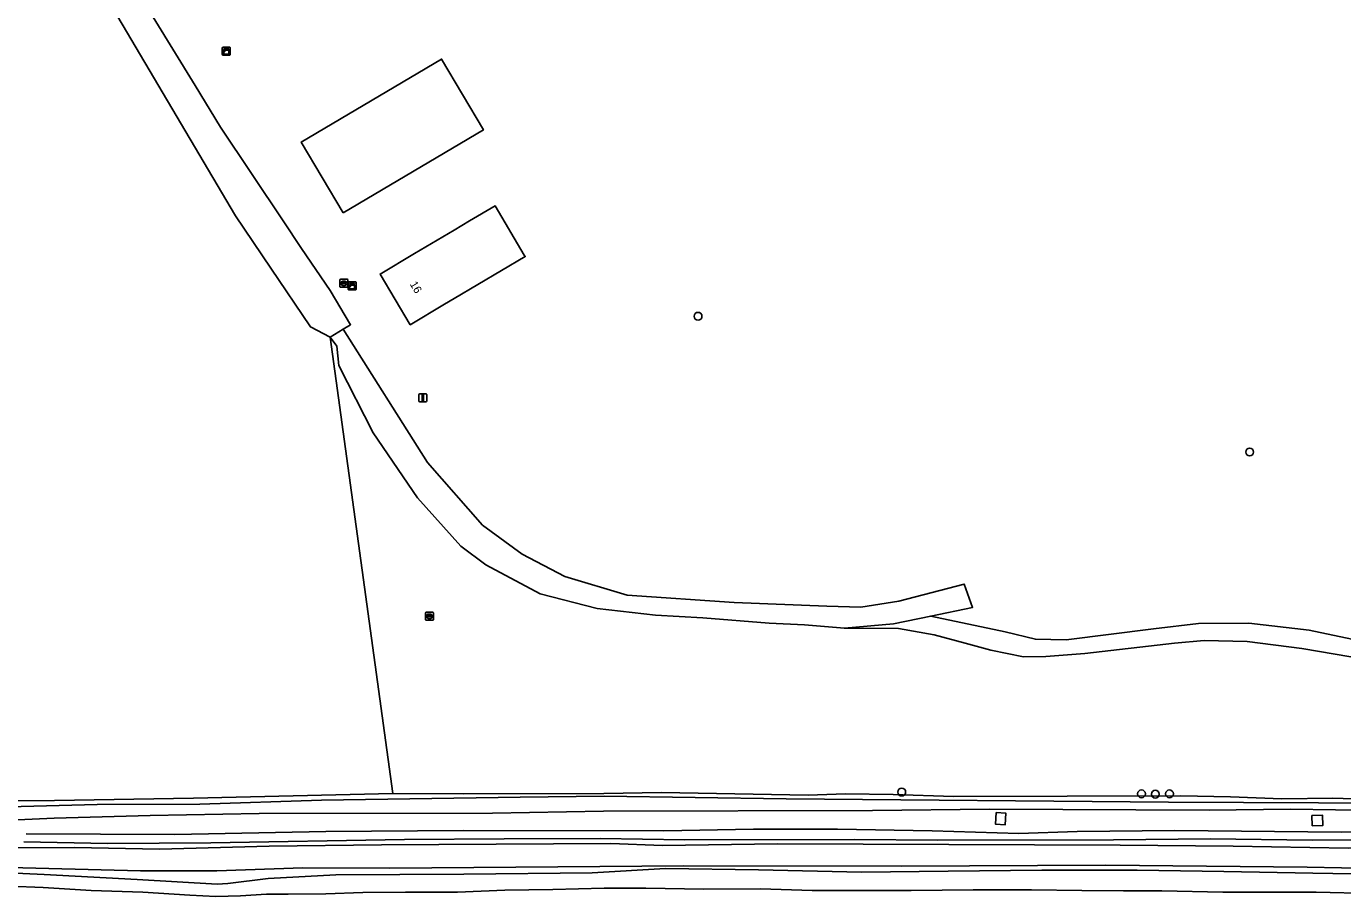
# Model space of a CAD drawing. Extents: x 160203 to 161530, y 379528 to 381797.
# Drawn here: x 160446.6 to 160611, y 379665.5 to 379774.3 of the extents above; entities that cross this region are included whole.
import ezdxf

# ---------------------------------------------------------------- set-up
doc = ezdxf.new("R2010")
doc.units = 0
for name, color, linetype in [('IMGEO_Boom', 7, 'Continuous'), ('IMGEO_Grasland_overig', 7, 'Continuous'), ('IMGEO_Groenvoorziening', 7, 'Continuous'), ('IMGEO_Hek', 7, 'Continuous'), ('IMGEO_Kast', 7, 'Continuous'), ('IMGEO_Lichtmast', 7, 'Continuous'), ('IMGEO_Pand', 7, 'Continuous'), ('IMGEO_Pand_nummerreeks', 7, 'Continuous'), ('IMGEO_Rijbaan_lokaal_gesloten', 7, 'Continuous'), ('IMGEO_Rijbaan_lokaal_halfverhard', 7, 'Continuous'), ('IMGEO_Rijbaan_lokaal_onverhard', 7, 'Continuous'), ('IMGEO_Rioolput', 7, 'Continuous'), ('IMGEO_Voetpad_open', 7, 'Continuous')]:
    doc.layers.add(name, color=color, linetype=linetype)

msp = doc.modelspace()

# ---------------------------------------------------------------- linework, layer by layer
at = {"layer": 'IMGEO_Boom'}
for centre in [(160530.49, 379738.08), (160599.41, 379721.11), (160555.94, 379678.6), (160585.9, 379678.38), (160587.63, 379678.34), (160589.39, 379678.38)]:
    msp.add_circle(centre, 0.489, dxfattribs=at)
at = {"layer": 'IMGEO_Grasland_overig'}
for points in [[(160450.12, 379795.52), (160467.63, 379766.93), (160470.83, 379761.7), (160478.64, 379750), (160480.94, 379746.53), (160484.53, 379741.3), (160487.06, 379737.02), (160486.15, 379736.46), (160496.7, 379719.81), (160503.56, 379711.98), (160508.49, 379708.33), (160513.83, 379705.53), (160521.61, 379703.21), (160534.99, 379702.31), (160546.6, 379701.83), (160550.81, 379701.71), (160555.59, 379702.48), (160563.74, 379704.6), (160564.79, 379701.69), (160559.56, 379700.59), (160568.86, 379698.64), (160572.64, 379697.7), (160576.48, 379697.62), (160587.41, 379699.01), (160593.03, 379699.68), (160599.33, 379699.71), (160606.84, 379698.83), (160615.35, 379697.05)], [(160472.68, 379750.63), (160447.21, 379793.79)], [(160424.45, 379677.34), (160450.09, 379677.56), (160467.43, 379677.83), (160492.33, 379678.43), (160484.53, 379735.46), (160482.04, 379736.75), (160477.11, 379744.07), (160472.68, 379750.63)], [(160617.93, 379694.49), (160605.92, 379696.56), (160599.09, 379697.42), (160593.73, 379697.54), (160590.01, 379697.2), (160578.8, 379695.94), (160573.94, 379695.55), (160571.17, 379695.52), (160567.06, 379696.36), (160563.85, 379697.23), (160560, 379698.24), (160555.54, 379699.04), (160548.78, 379699.07), (160543.77, 379699.51), (160539.38, 379699.73), (160531.09, 379700.4), (160525.19, 379700.71), (160517.9, 379701.55), (160510.76, 379703.37), (160503.96, 379707), (160500.86, 379709.33), (160495.45, 379715.4), (160489.91, 379723.51), (160485.58, 379731.93), (160485.34, 379734.34), (160484.53, 379735.46), (160492.33, 379678.43), (160501.15, 379678.37), (160518.7, 379678.42), (160525.94, 379678.55), (160544.26, 379678.22), (160548.9, 379678.37), (160554.86, 379678.29), (160562.39, 379678.04), (160590.8, 379678.12), (160597.04, 379678), (160603.45, 379677.76), (160609.81, 379677.82), (160617.65, 379677.59)], [(160784.17, 379667.9), (160765.94, 379668.23), (160737.86, 379669.18), (160701.05, 379669.65), (160671.71, 379670.49), (160660.93, 379671.01), (160649.83, 379671.31), (160624.32, 379671.66), (160611.72, 379671.59), (160597.36, 379671.85), (160583.22, 379671.96), (160540.43, 379672.12), (160526.04, 379671.93), (160519.57, 379672.16), (160490.95, 379672.02), (160476.88, 379671.86), (160463.21, 379671.47), (160452.55, 379671.69), (160440.92, 379671.64)], [(160442.8, 379669.22), (160460.83, 379668.76), (160470.36, 379668.77), (160481.1, 379669.13), (160491.99, 379669.11), (160528.7, 379669.4), (160555.86, 379669.34), (160581.45, 379669.48), (160606.62, 379669.23), (160619.49, 379668.98), (160631.78, 379668.92), (160643.42, 379668.69), (160654.24, 379668.27), (160666.84, 379668.02), (160681.18, 379667.54), (160711.08, 379667.31), (160739.31, 379666.82), (160755.63, 379666.39), (160768.72, 379665.89), (160783.83, 379665.68)], [(160619.73, 379668.24), (160607.32, 379668.46), (160596.17, 379668.66), (160585.35, 379668.82), (160573.45, 379668.83), (160561.73, 379668.7), (160550.92, 379668.6), (160538.03, 379668.88), (160526.4, 379669.03), (160517.27, 379668.52), (160501.23, 379668.35), (160485.24, 379668.25), (160476.77, 379667.79), (160471.74, 379667.18), (160470.4, 379667.09), (160460.4, 379667.67), (160448.8, 379668.28), (160442.53, 379668.6)], [(160444.44, 379666.85), (160448.66, 379666.68), (160454.64, 379666.28), (160461.09, 379666.07), (160466.97, 379665.71), (160470.23, 379665.53), (160473.31, 379665.65), (160476.55, 379665.83), (160479.28, 379665.84), (160483.98, 379665.89), (160488.59, 379666.06), (160493.94, 379666.1), (160500.43, 379666.11), (160506.35, 379666.33), (160512.36, 379666.42), (160518.76, 379666.57), (160523.98, 379666.61), (160531.2, 379666.48), (160538.3, 379666.49), (160544.76, 379666.3), (160550.39, 379666.31), (160557.13, 379666.31), (160564.86, 379666.38), (160572.16, 379666.39), (160578.43, 379666.31), (160583.64, 379666.27), (160588.44, 379666.27), (160596.07, 379666.11), (160601.88, 379666.09), (160607.73, 379666.09), (160614.68, 379665.91)], [(160614.68, 379665.91), (160607.73, 379666.09), (160601.88, 379666.09), (160596.07, 379666.11), (160588.44, 379666.27), (160583.64, 379666.27), (160578.43, 379666.31), (160572.16, 379666.39), (160564.86, 379666.38), (160557.13, 379666.31), (160550.39, 379666.31), (160544.76, 379666.3), (160538.3, 379666.49), (160531.2, 379666.48), (160523.98, 379666.61), (160518.76, 379666.57), (160512.36, 379666.42), (160506.35, 379666.33), (160500.43, 379666.11), (160493.94, 379666.1), (160488.59, 379666.06), (160483.98, 379665.89), (160479.28, 379665.84), (160476.55, 379665.83), (160473.31, 379665.65), (160470.23, 379665.53), (160466.97, 379665.71), (160461.09, 379666.07), (160454.64, 379666.28), (160448.66, 379666.68), (160444.44, 379666.85)]]:
    msp.add_lwpolyline(points, dxfattribs=at)
for points in [[(160486.15, 379750.99), (160480.9, 379759.85), (160498.43, 379770.23), (160503.67, 379761.37)], [(160508.78, 379745.73), (160508.9, 379745.54), (160500, 379740.28), (160498.82, 379739.58), (160494.52, 379737.02), (160490.76, 379743.35), (160495.05, 379745.91), (160500, 379748.85), (160501.94, 379750), (160505.12, 379751.89)]]:
    msp.add_lwpolyline(points, close=True, dxfattribs=at)
at = {"layer": 'IMGEO_Groenvoorziening'}
for points in [[(160617.65, 379677.59), (160609.81, 379677.82), (160603.45, 379677.76), (160597.04, 379678), (160590.8, 379678.12), (160562.39, 379678.04), (160554.86, 379678.29), (160548.9, 379678.37), (160544.26, 379678.22), (160525.94, 379678.55), (160518.7, 379678.42), (160501.15, 379678.37), (160492.33, 379678.43), (160467.43, 379677.83), (160450.09, 379677.56), (160424.45, 379677.34)], [(160441.12, 379676.68), (160455.42, 379677.06), (160468.24, 379677.1), (160483.42, 379677.59), (160508.26, 379677.98), (160518.76, 379678.1), (160541.49, 379677.74), (160589.29, 379677.35), (160636.08, 379677.12), (160651.83, 379677.17), (160666.86, 379676.84), (160695.82, 379676.79), (160724.57, 379675.97), (160738, 379675.79), (160762.64, 379675.16), (160784.4, 379674.19)], [(160784.4, 379674.19), (160762.64, 379675.16), (160738, 379675.79), (160724.57, 379675.97), (160695.82, 379676.79), (160666.86, 379676.84), (160651.83, 379677.17), (160636.08, 379677.12), (160589.29, 379677.35), (160541.49, 379677.74), (160518.76, 379678.1), (160508.26, 379677.98), (160483.42, 379677.59), (160468.24, 379677.1), (160455.42, 379677.06), (160441.12, 379676.68)], [(160782.51, 379673.2), (160766.24, 379673.54), (160749.57, 379673.53), (160734.81, 379673.91), (160717.03, 379674.91), (160688.91, 379675.62), (160653.12, 379675.94), (160638.64, 379675.84), (160626.99, 379676.14), (160604.5, 379676.47), (160594.36, 379676.34), (160566.92, 379676.46), (160552.27, 379676.29), (160518.66, 379676.21), (160504.81, 379675.98), (160475.63, 379675.94), (160462.02, 379675.67), (160450.05, 379675.33), (160434.47, 379674.64)], [(160434.47, 379674.64), (160450.05, 379675.33), (160462.02, 379675.67), (160475.63, 379675.94), (160504.81, 379675.98), (160518.66, 379676.21), (160552.27, 379676.29), (160566.92, 379676.46), (160594.36, 379676.34), (160604.5, 379676.47), (160626.99, 379676.14), (160638.64, 379675.84), (160653.12, 379675.94), (160688.91, 379675.62), (160717.03, 379674.91), (160734.81, 379673.91), (160749.57, 379673.53), (160766.24, 379673.54), (160782.51, 379673.2)], [(160779.34, 379669.05), (160754, 379670.17), (160743.81, 379670.41), (160733.3, 379670.12), (160723.85, 379670.33), (160713.24, 379670.92), (160707.37, 379671.13), (160700.01, 379671.6), (160688.6, 379671.13), (160673.16, 379671.38), (160633.97, 379672.61), (160621.89, 379672.69), (160607.24, 379672.58), (160594.52, 379672.76), (160582.39, 379672.64), (160560.38, 379672.61), (160550.09, 379672.69), (160528.85, 379672.64), (160518.26, 379672.79), (160506.28, 379672.77), (160493.79, 379672.67), (160469.61, 379672.26), (160456.71, 379672.17), (160446.26, 379672.37)], [(160446.26, 379672.37), (160456.71, 379672.17), (160469.61, 379672.26), (160493.79, 379672.67), (160506.28, 379672.77), (160518.26, 379672.79), (160528.85, 379672.64), (160550.09, 379672.69), (160560.38, 379672.61), (160582.39, 379672.64), (160594.52, 379672.76), (160607.24, 379672.58), (160621.89, 379672.69), (160633.97, 379672.61), (160673.16, 379671.38), (160688.6, 379671.13), (160700.01, 379671.6), (160707.37, 379671.13), (160713.24, 379670.92), (160723.85, 379670.33), (160733.3, 379670.12), (160743.81, 379670.41), (160754, 379670.17), (160779.34, 379669.05)], [(160446.52, 379673.38), (160465.1, 379673.28), (160483.96, 379673.66), (160501.12, 379673.81), (160526.23, 379673.77), (160537.43, 379673.98), (160547.91, 379673.98), (160559.73, 379673.77), (160570.58, 379673.44), (160577.84, 379673.67), (160590.06, 379673.81), (160610.83, 379673.6), (160624.03, 379673.72), (160637.66, 379673.43), (160664.39, 379673.11), (160678.73, 379672.76), (160687.43, 379672.72), (160699.17, 379673.1), (160721.63, 379672.13), (160733.98, 379671.8), (160745.18, 379671.62), (160758.24, 379671.16), (160779.42, 379670.28)], [(160779.42, 379670.28), (160758.24, 379671.16), (160745.18, 379671.62), (160733.98, 379671.8), (160721.63, 379672.13), (160699.17, 379673.1), (160687.43, 379672.72), (160678.73, 379672.76), (160664.39, 379673.11), (160637.66, 379673.43), (160624.03, 379673.72), (160610.83, 379673.6), (160590.06, 379673.81), (160577.84, 379673.67), (160570.58, 379673.44), (160559.73, 379673.77), (160547.91, 379673.98), (160537.43, 379673.98), (160526.23, 379673.77), (160501.12, 379673.81), (160483.96, 379673.66), (160465.1, 379673.28), (160446.52, 379673.38)], [(160440.92, 379671.64), (160452.55, 379671.69), (160463.21, 379671.47), (160476.88, 379671.86), (160490.95, 379672.02), (160519.57, 379672.16), (160526.04, 379671.93), (160540.43, 379672.12), (160583.22, 379671.96), (160597.36, 379671.85), (160611.72, 379671.59), (160624.32, 379671.66), (160649.83, 379671.31), (160660.93, 379671.01), (160671.71, 379670.49), (160701.05, 379669.65), (160737.86, 379669.18), (160765.94, 379668.23), (160784.17, 379667.9)], [(160783.83, 379665.68), (160768.72, 379665.89), (160755.63, 379666.39), (160739.31, 379666.82), (160711.08, 379667.31), (160681.18, 379667.54), (160666.84, 379668.02), (160654.24, 379668.27), (160643.42, 379668.69), (160631.78, 379668.92), (160619.49, 379668.98), (160606.62, 379669.23), (160581.45, 379669.48), (160555.86, 379669.34), (160528.7, 379669.4), (160491.99, 379669.11), (160481.1, 379669.13), (160470.36, 379668.77), (160460.83, 379668.76), (160442.8, 379669.22)], [(160442.53, 379668.6), (160448.8, 379668.28), (160460.4, 379667.67), (160470.4, 379667.09), (160471.74, 379667.18), (160476.77, 379667.79), (160485.24, 379668.25), (160501.23, 379668.35), (160517.27, 379668.52), (160526.4, 379669.03), (160538.03, 379668.88), (160550.92, 379668.6), (160561.73, 379668.7), (160573.45, 379668.83), (160585.35, 379668.82), (160596.17, 379668.66), (160607.32, 379668.46), (160619.73, 379668.24)]]:
    msp.add_lwpolyline(points, dxfattribs=at)
for points in [[(160568.86, 379674.5), (160567.66, 379674.58), (160567.74, 379676.03), (160568.95, 379675.95)], [(160607.23, 379674.39), (160607.2, 379675.67), (160608.52, 379675.7), (160608.55, 379674.41)]]:
    msp.add_lwpolyline(points, close=True, dxfattribs=at)
at = {"layer": 'IMGEO_Hek'}
msp.add_lwpolyline([(160617.65, 379677.59), (160609.81, 379677.82), (160603.45, 379677.76), (160597.04, 379678), (160590.8, 379678.12), (160562.39, 379678.04), (160554.86, 379678.29), (160548.9, 379678.37), (160544.26, 379678.22), (160525.94, 379678.55), (160518.7, 379678.42), (160501.15, 379678.37), (160492.33, 379678.43), (160467.43, 379677.83), (160450.09, 379677.56), (160424.45, 379677.34)], dxfattribs=at)
at = {"layer": 'IMGEO_Kast'}
for p, q in [((160471.04, 379770.79), (160471.04, 379771.63)), ((160471.04, 379771.63), (160471.04, 379770.79)), ((160471.12, 379771.71), (160471.96, 379771.71)), ((160471.96, 379771.71), (160471.12, 379771.71)), ((160472.04, 379771.64), (160472.04, 379770.8)), ((160472.04, 379770.8), (160472.04, 379771.64)), ((160471.97, 379770.71), (160471.13, 379770.71)), ((160471.13, 379770.71), (160471.97, 379770.71)), ((160486.76, 379741.44), (160486.76, 379742.28)), ((160486.76, 379742.28), (160486.76, 379741.44)), ((160486.83, 379742.37), (160487.67, 379742.37)), ((160487.67, 379742.37), (160486.83, 379742.37)), ((160487.76, 379742.29), (160487.76, 379741.45)), ((160487.76, 379741.45), (160487.76, 379742.29)), ((160487.68, 379741.37), (160486.84, 379741.37)), ((160486.84, 379741.37), (160487.68, 379741.37))]:
    msp.add_line(p, q, dxfattribs=at)
for points in [[(160471.24, 379771.5), (160471.84, 379771.5), (160471.84, 379771.42), (160471.24, 379771.42), (160471.24, 379771.5)], [(160471.24, 379771.33), (160471.84, 379771.33), (160471.84, 379770.84), (160471.24, 379770.84), (160471.24, 379771.33)], [(160486.95, 379742.16), (160487.55, 379742.16), (160487.55, 379742.07), (160486.95, 379742.07), (160486.95, 379742.16)], [(160486.95, 379741.98), (160487.55, 379741.98), (160487.55, 379741.49), (160486.95, 379741.49), (160486.95, 379741.98)]]:
    msp.add_lwpolyline(points, dxfattribs=at)
for centre in [(160471.32, 379771.18), (160487.04, 379741.83)]:
    msp.add_circle(centre, 0.0377, dxfattribs=at)
for centre, start, end in [((160471.12, 379771.63), 92.4484, 184.2845), ((160471.12, 379771.63), 92.4484, 184.2845), ((160471.96, 379771.63), 2.4484, 94.2845), ((160471.96, 379771.63), 2.4484, 94.2845), ((160471.12, 379770.79), 182.4484, 274.2845), ((160471.12, 379770.79), 182.4484, 274.2845), ((160471.96, 379770.79), 272.4484, 4.2845), ((160471.96, 379770.79), 272.4484, 4.2845), ((160486.84, 379742.29), 92.4484, 184.2845), ((160486.84, 379742.29), 92.4484, 184.2845), ((160487.68, 379742.29), 2.4484, 94.2845), ((160487.68, 379742.29), 2.4484, 94.2845), ((160486.84, 379741.45), 182.4484, 274.2845), ((160486.84, 379741.45), 182.4484, 274.2845), ((160487.68, 379741.45), 272.4484, 4.2845), ((160487.68, 379741.45), 272.4484, 4.2845)]:
    msp.add_arc(centre, 0.0779, start, end, dxfattribs=at)
at = {"layer": 'IMGEO_Lichtmast'}
for p, q in [((160495.69, 379728.38), (160496.48, 379728.38)), ((160496.48, 379728.38), (160495.69, 379728.38)), ((160495.59, 379727.49), (160495.59, 379728.28)), ((160495.59, 379728.28), (160495.59, 379727.49)), ((160496.48, 379727.39), (160495.69, 379727.39)), ((160495.69, 379727.39), (160496.48, 379727.39)), ((160496.58, 379728.28), (160496.58, 379727.49)), ((160496.58, 379727.49), (160496.58, 379728.28))]:
    msp.add_line(p, q, dxfattribs=at)
msp.add_lwpolyline([(160496.01, 379728.26), (160496.16, 379728.26), (160496.16, 379727.51), (160496.01, 379727.51), (160496.01, 379728.26)], dxfattribs=at)
for centre, start, end in [((160495.69, 379728.28), 90, 180), ((160495.69, 379728.28), 90, 180), ((160496.48, 379728.28), 0, 90), ((160496.48, 379728.28), 360, 90), ((160495.69, 379727.49), 180, 270), ((160495.69, 379727.49), 180, 270), ((160496.48, 379727.49), 270, 0), ((160496.48, 379727.49), 270, 0)]:
    msp.add_arc(centre, 0.1, start, end, dxfattribs=at)
at = {"layer": 'IMGEO_Pand'}
for points in [[(160486.15, 379750.99), (160503.67, 379761.37), (160498.43, 379770.23), (160480.9, 379759.85)], [(160505.12, 379751.89), (160501.94, 379750), (160500, 379748.85), (160495.05, 379745.91), (160490.76, 379743.35), (160494.52, 379737.02), (160498.82, 379739.58), (160500, 379740.28), (160508.9, 379745.54), (160508.78, 379745.73)]]:
    msp.add_lwpolyline(points, close=True, dxfattribs=at)
at = {"layer": 'IMGEO_Rijbaan_lokaal_gesloten'}
msp.add_lwpolyline([(160447.21, 379793.79), (160472.68, 379750.63), (160477.11, 379744.07), (160482.04, 379736.75), (160484.53, 379735.46), (160486.15, 379736.46), (160487.06, 379737.02), (160484.53, 379741.3), (160480.94, 379746.53), (160478.64, 379750), (160470.83, 379761.7), (160467.63, 379766.93), (160450.12, 379795.52)], dxfattribs=at)
at = {"layer": 'IMGEO_Rijbaan_lokaal_halfverhard'}
msp.add_lwpolyline([(160486.15, 379736.46), (160484.53, 379735.46), (160485.34, 379734.34), (160485.58, 379731.93), (160489.91, 379723.51), (160495.45, 379715.4), (160500.86, 379709.33), (160503.96, 379707), (160510.76, 379703.37), (160517.9, 379701.55), (160525.19, 379700.71), (160531.09, 379700.4), (160539.38, 379699.73), (160543.77, 379699.51), (160548.78, 379699.07), (160554.91, 379699.63), (160559.56, 379700.59), (160564.79, 379701.69), (160563.74, 379704.6), (160555.59, 379702.48), (160550.81, 379701.71), (160546.6, 379701.83), (160534.99, 379702.31), (160521.61, 379703.21), (160513.83, 379705.53), (160508.49, 379708.33), (160503.56, 379711.98), (160496.7, 379719.81)], close=True, dxfattribs=at)
at = {"layer": 'IMGEO_Rijbaan_lokaal_onverhard'}
msp.add_lwpolyline([(160615.35, 379697.05), (160606.84, 379698.83), (160599.33, 379699.71), (160593.03, 379699.68), (160587.41, 379699.01), (160576.48, 379697.62), (160572.64, 379697.7), (160568.86, 379698.64), (160559.56, 379700.59), (160554.91, 379699.63), (160548.78, 379699.07), (160555.54, 379699.04), (160560, 379698.24), (160563.85, 379697.23), (160567.06, 379696.36), (160571.17, 379695.52), (160573.94, 379695.55), (160578.8, 379695.94), (160590.01, 379697.2), (160593.73, 379697.54), (160599.09, 379697.42), (160605.92, 379696.56), (160617.93, 379694.49)], dxfattribs=at)
at = {"layer": 'IMGEO_Rioolput'}
for p, q in [((160485.74, 379741.77), (160485.74, 379742.63)), ((160485.81, 379742.7), (160486.66, 379742.7)), ((160486.66, 379741.7), (160485.81, 379741.7)), ((160486, 379742.19), (160486, 379742.21)), ((160486.04, 379742.24), (160486.44, 379742.24)), ((160486.43, 379742.16), (160486.04, 379742.16)), ((160486.25, 379741.92), (160486.22, 379741.92)), ((160486.23, 379742.48), (160486.25, 379742.48)), ((160486.48, 379742.21), (160486.48, 379742.19)), ((160486.74, 379742.63), (160486.74, 379741.77)), ((160496.43, 379700.15), (160496.43, 379701)), ((160496.5, 379701.08), (160497.36, 379701.08)), ((160496.69, 379700.57), (160496.69, 379700.58)), ((160496.73, 379700.62), (160497.13, 379700.62)), ((160497.13, 379700.53), (160496.73, 379700.53)), ((160496.92, 379700.86), (160496.94, 379700.86)), ((160497.17, 379700.58), (160497.17, 379700.57)), ((160497.43, 379701), (160497.43, 379700.15)), ((160497.36, 379700.08), (160496.5, 379700.08)), ((160496.94, 379700.3), (160496.91, 379700.3))]:
    msp.add_line(p, q, dxfattribs=at)
for points in [[(160485.74, 379741.77), (160485.74, 379742.63)], [(160485.81, 379742.7), (160486.66, 379742.7)], [(160486.66, 379741.7), (160485.81, 379741.7)], [(160486.74, 379742.63), (160486.74, 379741.77)], [(160496.43, 379700.15), (160496.43, 379701)], [(160496.5, 379701.08), (160497.36, 379701.08)], [(160497.43, 379701), (160497.43, 379700.15)], [(160497.36, 379700.08), (160496.5, 379700.08)]]:
    msp.add_lwpolyline(points, dxfattribs=at)
for centre, radius, start, end in [((160485.81, 379742.62), 0.0765, 91.552, 178.448), ((160485.81, 379742.62), 0.0765, 91.552, 178.448), ((160485.81, 379741.78), 0.0765, 181.552, 268.448), ((160485.81, 379741.78), 0.0765, 181.552, 268.448), ((160486.04, 379742.2), 0.0403, 85.8775, 175.7526), ((160486.03, 379742.19), 0.0366, 178.938, 274.7102), ((160486.44, 379742.2), 0.043, 264.8664, 352.4533), ((160486.44, 379742.2), 0.0386, 1.7309, 96.639), ((160486.66, 379742.62), 0.0765, 1.552, 88.448), ((160486.66, 379742.62), 0.0765, 1.552, 88.448), ((160486.66, 379741.78), 0.0765, 271.552, 358.448), ((160486.66, 379741.78), 0.0765, 271.552, 358.448), ((160496.51, 379701), 0.0765, 91.552, 178.448), ((160496.51, 379701), 0.0765, 91.552, 178.448), ((160496.73, 379700.58), 0.0403, 85.8775, 175.7526), ((160496.72, 379700.57), 0.0366, 178.938, 274.7102), ((160497.13, 379700.58), 0.0386, 1.7309, 96.639), ((160497.13, 379700.58), 0.043, 264.8664, 352.4533), ((160497.35, 379701), 0.0765, 1.552, 88.448), ((160497.35, 379701), 0.0765, 1.552, 88.448), ((160496.51, 379700.15), 0.0765, 181.552, 268.448), ((160496.51, 379700.15), 0.0765, 181.552, 268.448), ((160497.35, 379700.15), 0.0765, 271.552, 358.448), ((160497.35, 379700.15), 0.0765, 271.552, 358.448)]:
    msp.add_arc(centre, radius, start, end, dxfattribs=at)
for centre, major_axis, ratio, start_param, end_param in [((160486.22, 379742.2), (-0.387, 0.002), 0.722429, 4.712389, 7.853982), ((160486.25, 379742.2), (-0.39, 0.002), 0.717154, 1.570796, 4.712389), ((160496.92, 379700.58), (-0.387, 0.002), 0.722429, 4.712389, 7.853982), ((160496.94, 379700.58), (-0.39, 0.002), 0.717154, 1.570796, 4.712389)]:
    msp.add_ellipse(centre, major_axis=major_axis, ratio=ratio, start_param=start_param, end_param=end_param, dxfattribs=at)
at = {"layer": 'IMGEO_Voetpad_open'}
for points in [[(160568.95, 379675.95), (160567.74, 379676.03), (160567.66, 379674.58), (160568.86, 379674.5)], [(160608.55, 379674.41), (160608.52, 379675.7), (160607.2, 379675.67), (160607.23, 379674.39)]]:
    msp.add_lwpolyline(points, close=True, dxfattribs=at)

# ---------------------------------------------------------------- texts
at = {"layer": 'IMGEO_Pand_nummerreeks'}
msp.add_text('16', height=1, rotation=300.7382, dxfattribs=at).set_placement((160494.43, 379742.1))

doc.saveas('drawing.dxf')
